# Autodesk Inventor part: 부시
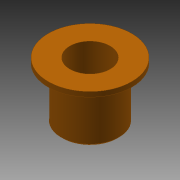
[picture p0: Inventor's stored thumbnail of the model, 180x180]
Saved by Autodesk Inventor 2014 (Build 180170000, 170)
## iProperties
Created: 2015-10
Part Number: 부시
Document SubType Name: Modeling
Designer: mdu
Density: 7.86 g/cm^3
Material: 황동, 연질
Mass: 246.97 g
Surface Area: 129.264 cm^2
Volume: 31.4212 cm^3
Appearance: 주황색
Author: mdu
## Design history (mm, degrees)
sketch "스케치1"
  geometry: C1 r 31 at (0, 0) reference; C2 r 25 at (0, 0) reference; C3 r 30 at (0, 0) reference; C4 r 26 at (0, 0); C5 r 18 at (0, 0); 1 further point
  constraints: 2 centre point, 2 coincident
  dimensions: "d20" = 5 radial gap between concentric circles of C1 C4; "d21" = 8 radial gap between concentric circles of C5 C4
  node "참조1"
  node "참조2"
  node "참조4"
extrude "돌출1" new body sketch "스케치1" distance "d0" = 10; taper "d1" = 0 deg
extrude "돌출2" join sketch "스케치1" distance "d2" = 35; taper "d3" = 0 deg
sketch "스케치4"
  geometry: C1 r 12.5 at (0, 0); 1 further point
  constraints: 1 centre point, 1 coincident
  dimensions: "d24" = 25 diameter of C1
extrude "돌출5" cut sketch "스케치4" stored distance "d25" = 10; taper "d26" = 0 deg
chamfer "모따기1" distance "d6" = 1; stored, may be unused: second distance "d7" = 2, angle "d8" = 45 deg
node "솔리드1"
